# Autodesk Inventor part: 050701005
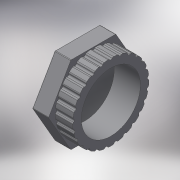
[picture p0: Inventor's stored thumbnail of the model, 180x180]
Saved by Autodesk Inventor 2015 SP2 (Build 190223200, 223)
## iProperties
Created: 2017-10
Part Number: 050701005
Material: Generic
Description: PLASSON THREADED CAP PVC 1/2"
Document SubType Name: Modeling
Designer: KIM
Density: 1 g/cm^3
Appearance: Default
Author: KIM
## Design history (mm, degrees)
derived "050701.ipt"
feature "Solid1::050701.ipt"
tag "TaggingFeature1"
body "Solid1"
other parameters: "d0" = 27, "d1" = 29.4, "d2" = 1, "d3" = 12, "d5" = 19, "d6" = 18.631, "d7" = 5.7, "d10" = 0, "d11" = 1.2, "d13" = 0, "d14" = 0.6, "d16" = 360 deg, "d18" = 0.3, "G_" = 18.631, "B_" = 12, "Lt_" = 19, "H_" = 27
